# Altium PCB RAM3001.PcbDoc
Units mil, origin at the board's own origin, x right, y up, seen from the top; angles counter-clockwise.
Board outline 3500 x 2000 mil, 2 copper layers (Top Layer, Bottom Layer), stack 64.8 mil thick; 33 components, 89 nets, 343 pads, 69 vias.
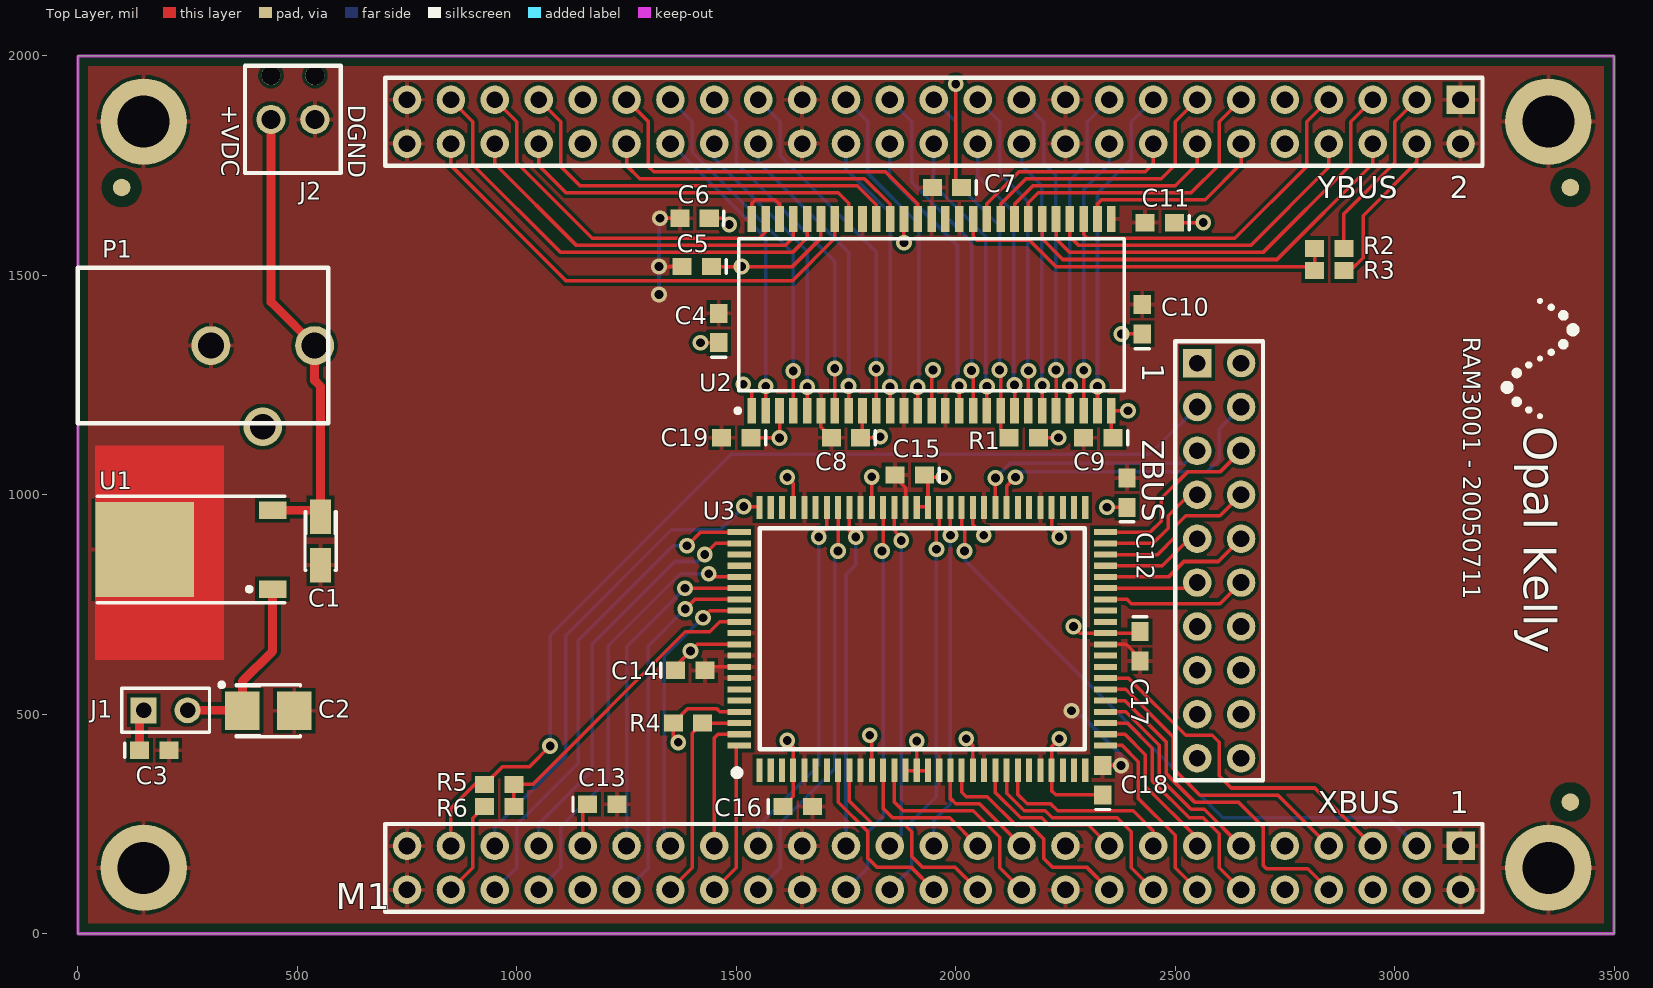
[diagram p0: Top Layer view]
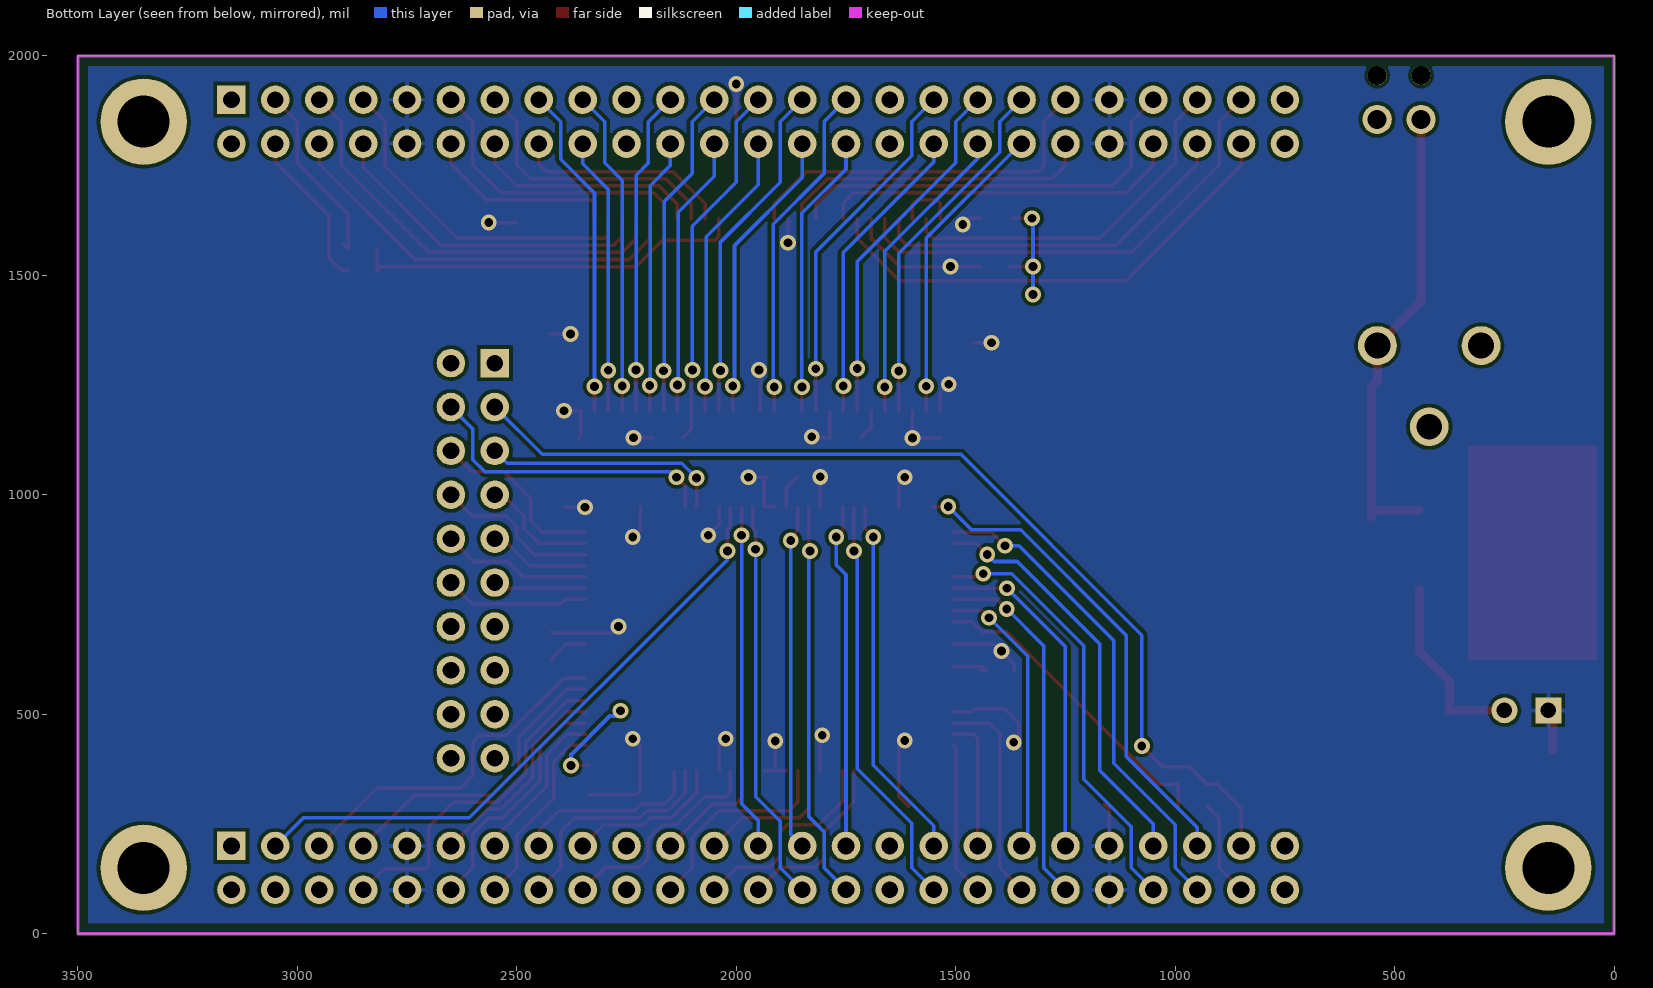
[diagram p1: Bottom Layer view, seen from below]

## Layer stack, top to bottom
Top Layer: signal copper 1.4
Dielectric: core 62, FR-4, Dk 4.8
Bottom Layer: signal copper 1.4

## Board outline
0,0 3500,0 3500,2000 0,2000

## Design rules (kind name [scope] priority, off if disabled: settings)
Clearance "Polygon Clearance" [InPolygon vs ((Not PadIsPlated) And (HoleSize = 0))] p1: gap=25
Clearance [All] p2: gap=8
ComponentClearance [All] p1: gap=10 collisioncheckmode=0 verticalgap=10
HoleSize [All] p1: absolutevalues=TRUE maxlimit=200 minlimit=1 maxpercent=80.000 minpercent=20.000
MinimumAnnularRing [All] p1: minimumring=8
PolygonConnect [All] p1: connectstyle=Relief reliefconductorwidth=10 reliefentries=4 polygonreliefangle="90 Angle"
RoutingVias [All] p1: holewidth=28 width=40 viastyle="Through Hole" minholewidth=20 minwidth=30 maxholewidth=40 maxwidth=70
SolderMaskExpansion [All] p1: expansion=4
TestPointUsage [All] p1: valid=0 allowmultiple=FALSE
Testpoint [All] p1: side=15 testpointundercomponent=TRUE minsize=40 maxsize=100 preferedsize=60 minholesize=0 maxholesize=40 preferedholesize=32 testpointgrid=1 style=1023 order=0123456789
Width [All] p1: maxlimit=24 minlimit=7 preferedwidth=7 toplayer_prefwidth=8 bottomlayer_prefwidth=10 minimp=50.000000 maximp=50.000000 favimp=50.000000
16 further rules are at their usual default settings.

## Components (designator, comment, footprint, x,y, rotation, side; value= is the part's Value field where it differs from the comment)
C1 "SM-A, 10v, 10%" TC3216-1206 553,895 r270 top
C2 "SM-A, 6.3v, 10%" TC3528-1411 434,508 r0 top
C3 "SM-0603, 10%, 16v" CC1608-0603 174,418 r0 top
C4 "SM-0603, 10%, 16v" CC1608-0603 1460,1380 r90 top
C5 "SM-0603, 10%, 16v" CC1608-0603 1410,1520 r180 top
C6 "SM-0603, 10%, 16v" CC1608-0603 1405,1630 r180 top
C7 "SM-0603, 10%, 16v" CC1608-0603 1980,1700 r180 top
C8 "SM-0603, 10%, 16v" CC1608-0603 1750,1130 r180 top
C9 "SM-0603, 10%, 16v" CC1608-0603 2325,1130 r180 top
C10 "SM-0603, 10%, 16v" CC1608-0603 2425,1400 r90 top
C11 "SM-0603, 10%, 16v" CC1608-0603 2465,1620 r180 top
C12 "SM-0603, 10%, 16v" CC1608-0603 2390,1005 r90 top
C13 "SM-0603, 10%, 16v" CC1608-0603 1195,295 r0 top
C14 "SM-0603, 10%, 16v" CC1608-0603 1395,600 r0 top
C15 "SM-0603, 10%, 16v" CC1608-0603 1895,1045 r180 top
C16 "SM-0603, 10%, 16v" CC1608-0603 1640,290 r0 top
C17 "SM-0603, 10%, 16v" CC1608-0603 2420,655 r270 top
C18 "SM-0603, 10%, 16v" CC1608-0603 2335,350 r90 top
C19 "SM-0603, 10%, 16v" CC1608-0603 1500,1130 r180 top
J1 "0.1\" spacing" HDR1X2 150,509 r0 top
J2 "2.54mm, 2-position" MPT-0.5/2-2.54 440,1855 r270 top
M1 "XEM3001" XEM3001MODULE 0,0 r0 top locked
P1 "2.1mm / 5.5mm" CUI-PJ102A 0,1340 r270 top locked
R1 "SM-0603, 5%, 1/10W" CR1608-0603 2155,1130 r180 top
R2 "SM-0603, 5%, 1/10W" CR1608-0603 2851,1561 r0 top
R3 "SM-0603, 5%, 1/10W" CR1608-0603 2851,1511 r0 top
R4 "SM-0603, 5%, 1/10W" CR1608-0603 1390,480 r0 top
R5 "SM-0603, 5%, 1/10W" CR1608-0603 960,340 r180 top
R6 "SM-0603, 5%, 1/10W" CR1608-0603 960,290 r180 top
U1 "1A, 3-pin DPAK" SIP-G3/Z11.05 298,875 r90 top
U2 "4Mbx16x4, TSOP" TSOP2-54 1945,1410 r0 top
U3 "2.5v/3.3v, 133 MHz, 256kx18" TQFP-100 1924,672 r0 top locked
? "OKLOGO" oklogotiny 3330.99,1441.5 r270 top

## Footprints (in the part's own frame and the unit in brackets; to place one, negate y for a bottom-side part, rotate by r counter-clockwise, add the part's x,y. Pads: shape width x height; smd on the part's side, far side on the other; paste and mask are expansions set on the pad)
CC1608-0603 [mm] "Chip Capacitor; Body 1.6 x 0.8 mm (LxW typ)"
  rect 1.1x1 smd: 1(-0.85,0) 2(0.85,0)
  silkscreen extent -1.7,-0.4 -1.7,0.4
CR1608-0603 [mm] "Chip Resistor; Body 1.6 x 0.8 mm (LxW typ)"
  rect 1.1x1 smd: 1(-0.85,0) 2(0.85,0)
CUI-PJ102A [mm] "2.1mm/5.5mm DC power jack"
  round 2.25 hole 1.5: 1(0,13.7) 2(0,7.7) 3(4.7,10.7)
  silkscreen extent -4.5,0 4.5,14.5
HDR1X2 [mm] "Connector; Header; 2 Position"
  rect 1.5x1.5 hole 0.9: 1(0,0)
  round 1.5 hole 0.9: 2(2.54,0)
  silkscreen extent -1.27,-1.27 3.81,1.27
MPT-0.5/2-2.54 [mm] "Terminal Block 1x2"
  round 1.1 hole 1.1: 0(-2.54,2.54) 0(-2.54,0)
  round 1.7 hole 1.1: 1(0,0) 2(0,2.54)
  silkscreen extent -3.1,-1.5 3.1,4.04
oklogotiny [mil] "Opal Kelly silkscreen logo (50 mil)."
  silkscreen extent -3,-82 266,83
SIP-G3/Z11.05 [mm] "D-PAK/TO-252-AA; 3 Leads (1 Cropped); Body 10.3 (inc. leads) x 6.7 mm (LxW max)"
  rect 1x1.6 smd: 1(-2.285,-3.7) 3(2.285,-3.7)
  rect 5.5x5.7 smd: 4(0,3.7)
  silkscreen extent -3.09,-4.4 3.09,6.45, body extent -3.3,-1.35 3.3,4.75, height 2.38
TC3216-1206 [mm] "Capacitor, SM Tantalum; Body 3.2 x 1.6 mm (LxW typ)"
  rect 2x1.2 smd: 1(-1.4,0) 2(1.4,0)
  silkscreen extent -1.7,-0.9 1.7,0.9
TC3528-1411 [mm] "Capacitor, SM Tantalum; Body 3.5 x 2.8 mm (LxW typ)"
  rect 2x2.2 smd: 1(-1.5,0) 2(1.5,0)
  silkscreen extent -2.82,-1.5 1.85,1.62
TQFP-100 [mm] "IPC Rectangular TQFP 100 Package"
  rect 0.35x1.35 smd: 1(-9.425,-7.6) 2(-8.775,-7.6) 3(-8.125,-7.6) 4(-7.475,-7.6) 5(-6.825,-7.6) 6(-6.175,-7.6) 7(-5.525,-7.6) 8(-4.875,-7.6) 9(-4.225,-7.6) 10(-3.575,-7.6) 11(-2.925,-7.6) 12(-2.275,-7.6) 13(-1.625,-7.6) 14(-0.975,-7.6) 15(-0.325,-7.6) 16(0.325,-7.6) 17(0.975,-7.6) 18(1.625,-7.6) 19(2.275,-7.6) 20(2.925,-7.6) 21(3.575,-7.6) 22(4.225,-7.6) 23(4.875,-7.6) 24(5.525,-7.6) 25(6.175,-7.6) 26(6.825,-7.6) 27(7.475,-7.6) 28(8.125,-7.6) 29(8.775,-7.6) 30(9.425,-7.6) 51(9.425,7.6) 52(8.775,7.6) 53(8.125,7.6) 54(7.475,7.6) 55(6.825,7.6) 56(6.175,7.6) 57(5.525,7.6) 58(4.875,7.6) 59(4.225,7.6) 60(3.575,7.6) 61(2.925,7.6) 62(2.275,7.6) 63(1.625,7.6) 64(0.975,7.6) 65(0.325,7.6) 66(-0.325,7.6) 67(-0.975,7.6) 68(-1.625,7.6) 69(-2.275,7.6) 70(-2.925,7.6) 71(-3.575,7.6) 72(-4.225,7.6) 73(-4.875,7.6) 74(-5.525,7.6) 75(-6.175,7.6) 76(-6.825,7.6) 77(-7.475,7.6) 78(-8.125,7.6) 79(-8.775,7.6) 80(-9.425,7.6)
  rect 1.35x0.35 smd: 31(10.6,-6.175) 32(10.6,-5.525) 33(10.6,-4.875) 34(10.6,-4.225) 35(10.6,-3.575) 36(10.6,-2.925) 37(10.6,-2.275) 38(10.6,-1.625) 39(10.6,-0.975) 40(10.6,-0.325) 41(10.6,0.325) 42(10.6,0.975) 43(10.6,1.625) 44(10.6,2.275) 45(10.6,2.925) 46(10.6,3.575) 47(10.6,4.225) 48(10.6,4.875) 49(10.6,5.525) 50(10.6,6.175) 81(-10.6,6.175) 82(-10.6,5.525) 83(-10.6,4.875) 84(-10.6,4.225) 85(-10.6,3.575) 86(-10.6,2.925) 87(-10.6,2.275) 88(-10.6,1.625) 89(-10.6,0.975) 90(-10.6,0.325) 91(-10.6,-0.325) 92(-10.6,-0.975) 93(-10.6,-1.625) 94(-10.6,-2.275) 95(-10.6,-2.925) 96(-10.6,-3.575) 97(-10.6,-4.225) 98(-10.6,-4.875) 99(-10.6,-5.525) 100(-10.6,-6.175)
  silkscreen extent -10.85,-7.87 9.4,6.4
TSOP2-54 [mm] "Plastic Small Outline; 54 Leads; Body Width 10.16 mm"
  rect 0.5x1.5 smd: 1(-10.4,-5.55) 2(-9.6,-5.55) 3(-8.8,-5.55) 4(-8,-5.55) 5(-7.2,-5.55) 6(-6.4,-5.55) 7(-5.6,-5.55) 8(-4.8,-5.55) 9(-4,-5.55) 10(-3.2,-5.55) 11(-2.4,-5.55) 12(-1.6,-5.55) 13(-0.8,-5.55) 14(0,-5.55) 15(0.8,-5.55) 16(1.6,-5.55) 17(2.4,-5.55) 18(3.2,-5.55) 19(4,-5.55) 20(4.8,-5.55) 21(5.6,-5.55) 22(6.4,-5.55) 23(7.2,-5.55) 24(8,-5.55) 25(8.8,-5.55) 26(9.6,-5.55) 27(10.4,-5.55) 28(10.4,5.55) 29(9.6,5.55) 30(8.8,5.55) 31(8,5.55) 32(7.2,5.55) 33(6.4,5.55) 34(5.6,5.55) 35(4.8,5.55) 36(4,5.55) 37(3.2,5.55) 38(2.4,5.55) 39(1.6,5.55) 40(0.8,5.55) 41(0,5.55) 42(-0.8,5.55) 43(-1.6,5.55) 44(-2.4,5.55) 45(-3.2,5.55) 46(-4,5.55) 47(-4.8,5.55) 48(-5.6,5.55) 49(-6.4,5.55) 50(-7.2,5.55) 51(-8,5.55) 52(-8.8,5.55) 53(-9.6,5.55) 54(-10.4,5.55)
  silkscreen extent -11.33,-5.67 11.15,4.4
XEM3001MODULE [mil]
  round 196.85 hole 118.11: 0(150,150) 0(150,1850) 0(3350,150) 0(3350,1850)
  rect 65x65 hole 38: X1(3150,200) Y1(3150,1900) Z1(2550,1300)
  round 65 hole 38: X2(3150,100) X3(3050,200) X4(3050,100) X5(2950,200) X6(2950,100) X7(2850,200) X8(2850,100) X9(2750,200) X10(2750,100) X11(2650,200) X12(2650,100) X13(2550,200) X14(2550,100) X15(2450,200) X16(2450,100) X17(2350,200) X18(2350,100) X19(2250,200) X20(2250,100) X21(2150,200) X22(2150,100) X23(2050,200) X24(2050,100) X25(1950,200) X26(1950,100) X27(1850,200) X28(1850,100) X29(1750,200) X30(1750,100) X31(1650,200) X32(1650,100) X33(1550,200) X34(1550,100) X35(1450,200) X36(1450,100) X37(1350,200) X38(1350,100) X39(1250,200) X40(1250,100) X41(1150,200) X42(1150,100) X43(1050,200) X44(1050,100) X45(950,200) X46(950,100) X47(850,200) X48(850,100) X49(750,200) X50(750,100) Y2(3150,1800) Y3(3050,1900) Y4(3050,1800) Y5(2950,1900) Y6(2950,1800) Y7(2850,1900) Y8(2850,1800) Y9(2750,1900) Y10(2750,1800) Y11(2650,1900) Y12(2650,1800) Y13(2550,1900) Y14(2550,1800) Y15(2450,1900) Y16(2450,1800) Y17(2350,1900) Y18(2350,1800) Y19(2250,1900) Y20(2250,1800) Y21(2150,1900) Y22(2150,1800) Y23(2050,1900) Y24(2050,1800) Y25(1950,1900) Y26(1950,1800) Y27(1850,1900) Y28(1850,1800) Y29(1750,1900) Y30(1750,1800) Y31(1650,1900) Y32(1650,1800) Y33(1550,1900) Y34(1550,1800) Y35(1450,1900) Y36(1450,1800) Y37(1350,1900) Y38(1350,1800) Y39(1250,1900) Y40(1250,1800) Y41(1150,1900) Y42(1150,1800) Y43(1050,1900) Y44(1050,1800) Y45(950,1900) Y46(950,1800) Y47(850,1900) Y48(850,1800) Y49(750,1900) Y50(750,1800) Z2(2650,1300) Z3(2550,1200) Z4(2650,1200) Z5(2550,1100) Z6(2650,1100) Z7(2550,1000) Z8(2650,1000) Z9(2550,900) Z10(2650,900) Z11(2550,800) Z12(2650,800) Z13(2550,700) Z14(2650,700) Z15(2550,600) Z16(2650,600) Z17(2550,500) Z18(2650,500) Z19(2550,400) Z20(2650,400)
  silkscreen extent 700,50 3200,1950

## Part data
C1 C2: library part "Capacitor Pol", "Tantalum capacitor"
C3 C4 C5 C6 C7 C8 C9 C10 C11 C12 C13 C14 C15 C16 C17 C18 C19: library part Capacitor, "Ceramic capacitor"
J1: library part "Jumper 1X2", "Header"
J2: library part "Terminal 1x2", "Terminal block connector"
M1: "XEM3001 Module Connector"
P1: library part DCPOWER, "DC power connector"
R1 R2 R3 R4 R5 R6: library part Resistor, "Thick-film resistor"
U1: library part LP8340CDT, "LDO Regulator"
U2: library part MT48LC16M16A2TG-7E, "32MB SDRAM"
U3: library part CY7C1352G, "4Mb Pipelined SRAM, NoBL"
?: "Opal Kelly PCB Logo"

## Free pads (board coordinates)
  round 40 smd mask+20: FD0(100,1700) FD1(3400,1700) FD2(3400,300)

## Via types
v1: diameter 36, hole 20, Top Layer to Bottom Layer, tented both sides, 69 vias

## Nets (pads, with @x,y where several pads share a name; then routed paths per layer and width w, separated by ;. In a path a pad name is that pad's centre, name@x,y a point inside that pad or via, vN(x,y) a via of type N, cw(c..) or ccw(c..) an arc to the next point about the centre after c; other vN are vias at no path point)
+3.3VDD: C3.1 C4.1 C5.1 C6.1 C7.1 C8.1 C9.1 C10.1 C11.1 C12.1 C13.1 C14.1 C15.1 C16.1 C17.1 C18.1 C19.1 J1.1 M1.X9 M1.X10 M1.X41 M1.X42 M1.Y9 M1.Y10 M1.Y41 M1.Y42 R1.1 R4.1 U2.1 U2.3 U2.9 U2.14 U2.27 U2.43 U2.49 U3.4 U3.11 U3.14 U3.15 U3.16 U3.20 U3.27 U3.41 U3.54 U3.61 U3.65 U3.66 U3.70 U3.77 U3.91 U3.97 | length 3266.3
  Top Layer w8: M1.X41 1150,283.46 C13.1 ; v1@1356.54,435.46 R4.1 1388.54,512 1456,512 1462.34,505.66 U3.97@1504.71,505.66 ; C14.1@1366.54,600 1366.54,614.54 1411.2,659.2 U3.91@1504.71,659.2 ; v1(1418.54,1346.54) C4.1 ; C5.1 1628,1520 1693.03,1585.03 U2.49 ; C6.1@1443.46,1630 1470,1630 v1(1484,1616) ; v1(1516,1252) 1535.55,1232.45 U2.1 ; C19.1 1598,1130 v1(1598.54,1129.46) U2.3 ; C16.1 1629.71,313.17 1629.71,426.29 v1(1616,440) ; v1(1616,1040) 1629.71,1026.29 U3.77@1629.71,973.18 ; U2.9 1787.52,1134.06 C8.1 1826,1130 v1(1828,1132) ; v1(1804,452) 1808.84,447.16 U3.11@1808.84,370.82 ; U3.70@1808.84,973.18 v1(1808.84,1040.84) ; v1(1882.01,1574.01) U2.43 ; U3.14@1885.61,370.82 U3.16@1936.8,370.82 ; U3.15@1911.2,370.82 v1(1911.2,439.2) ; U3.66@1911.2,973.18 1936.8,973.18 1936.8,1038.33 C15.1@1938.46,1040 ; C15.1@1928.46,1040 v1(1972,1040) ; U2.14 1945,1281 v1(1948,1284) ; v1(2000,1936) 2000,1713.46 C7.1 ; v1(2024,444) 2039.16,428.84 U3.20@2039.16,370.82 ; U3.61@2039.16,973.18 2039.16,932.84 v1(2064,908) ; R1.1 v1(2234,1130) ; U3.54@2218.29,973.18 2218.29,921.71 v1(2236,904) ; v1(2236,444) 2218.29,426.29 2218.29,325.71 2227.46,316.54 C18.1 ; v1(2268,700) 2283.2,684.8 2416.33,684.8 C17.1 ; v1(2344.47,971.53) C12.1 ; C9.1 2354.45,1134.02 U2.27 v1(2392.5,1191.5) ; v1(2377.46,1366.54) C10.1 ; C11.1 v1(2564,1620)
  Top Layer w20: C3.1@139,419.54 C3.1 140.54,499.54 J1.1
  other v1: 1368,436 1396,644 1512,1520
+VDC: C1.1 J2.1 P1.1 U1.3 | length 1084.8
  Top Layer w20: J2.1 440,1439.37 P1.1@553,1326.37 ; U1.3 542.1,964.96 C1.1@553,954.06 ; P1.1 539.37,1260.63 553,1247 C1.1
DGND: C1.2 C2.2 C3.2 C4.2 C5.2 C6.2 C7.2 C8.2 C9.2 C10.2 C11.2 C12.2 C13.2 C14.2 C15.2 C16.2 C17.2 C18.2 C19.2 J2.2 M1.0 M1.X1 M1.X2 M1.X19 M1.X20 M1.X31 M1.X32 M1.X49 M1.X50 M1.Y1 M1.Y2 M1.Y19 M1.Y20 M1.Y31 M1.Y32 M1.Y49 M1.Y50 P1.2 U1.4 U2.6 U2.12 U2.15 U2.28 U2.39 U2.41 U2.46 U2.52 U2.54 U3.5 U3.10 U3.17 U3.21 U3.26 U3.40 U3.55 U3.60 U3.67 U3.71 U3.76 U3.90 U3.92 U3.93 U3.94 | length 954.4
  Top Layer w8: v1(1324,1520) C5.2 ; v1(1326,1630) C6.2 ; C14.2 C14.2@1444,600 ; C14.2@1436.49,608.02 U3.93@1504.71,608.02 ; U2.54 1535.55,1663.55 1544,1672 1588,1672 1598.54,1661.46 U2.52 ; U2.6 1693.03,1153.5 C8.2 ; C15.2@1861.54,1040 1885.61,1015.92 U3.67@1885.61,973.18 ; C18.2 v1(2376.54,383.46) ; U3.40@2343.29,659.2 2388.8,659.2 2420,628 C17.2
  Bottom Layer w8: v1(1324,1456) 1324,1628 v1(1326,1630)
  Bottom Layer w10: v1@2264,496 2288,496 2376.54,407.46 v1(2376.54,383.46)
  other v1: 2264,508
NetC2_1: C2.1 J1.2 U1.1 | length 430.9
  Top Layer w20: J1.2 373.94,509 C2.1 374.94,574.94 443.67,643.67 U1.1
NetM1_X47: M1.X47 M1.Z3 R5.2 | length 2312.2
  Top Layer w8: M1.X47 850,286 904,340 R5.2 966.54,380 1028,380 v1(1076,428)
  Bottom Layer w8: v1(1076,428) 1076,680 1488,1092 2442,1092 M1.Z3
NetM1_X48: M1.X48 R6.2 | length 221.7
  Top Layer w8: M1.X48 900,150 900,263.46 R6.2
NetM1_Y3: M1.Y3 R2.2 | length 423.9
  Top Layer w8: R2.2@2896,1572.54 R2.2 2884.46,1640.46 3000,1756 3000,1850 M1.Y3
NetM1_Y4: M1.Y4 R3.2 | length 366.1
  Top Layer w8: R3.2 2899,1511 2928,1540 2928,1636 3050,1758 M1.Y4
SDRAM_A0: M1.Y21 U2.23 | length 743
  Top Layer w8: U2.23 v1(2228.46,1284.46)
  Bottom Layer w8: M1.Y21@2152,1900 M1.Y21 2200,1850 2200,1756 2228,1728 2228,1284.93 v1(2228.46,1284.46)
SDRAM_A1: M1.Y17 U2.24 | length 745.8
  Top Layer w8: U2.24 v1(2259.96,1248.04)
  Bottom Layer w8: v1(2259.96,1248.04) 2259.96,1715.96 2300,1756 2300,1850 M1.Y17
SDRAM_A2: M1.Y18 U2.25 | length 632.8
  Top Layer w8: U2.25 v1(2291.46,1283.46)
  Bottom Layer w8: v1(2291.46,1283.46) 2291.46,1695.46 2350,1754 M1.Y18
SDRAM_A3: M1.Y15 U2.26 | length 761.1
  Top Layer w8: U2.26 v1(2322.95,1246.95)
  Bottom Layer w8: v1(2322.95,1246.95) 2322.95,1686.95 2400,1764 2400,1850 M1.Y15
SDRAM_A4: M1.Y12 U2.29 | length 445.2
  Top Layer w8: U2.29 2322.95,1662.95 2332,1672 2568,1672 2650,1754 M1.Y12
SDRAM_A5: M1.Y7 U2.30 | length 788.7
  Top Layer w8: U2.30 2291.46,1592.54 2300,1584 2636,1584 2800,1748 2800,1850 M1.Y7
SDRAM_A6: M1.Y8 U2.31 | length 766.5
  Top Layer w8: U2.31 2259.96,1588.04 2280,1568 2672,1568 2850,1746 M1.Y8
SDRAM_A7: M1.Y5 U2.32 | length 981.1
  Top Layer w8: U2.32 2228.46,1583.54 2260,1552 2700,1552 2900,1752 2900,1850 M1.Y5
SDRAM_A8: M1.Y6 U2.33 | length 954.3
  Top Layer w8: U2.33 2196.97,1583.03 2244,1536 2732,1536 2950,1754 M1.Y6
SDRAM_A9: M1.Y11 U2.34 | length 676
  Top Layer w8: U2.34 2165.47,1665.47 2188,1688 2536,1688 2600,1752 2600,1850 M1.Y11
SDRAM_A10: M1.Y22 U2.22 | length 628
  Top Layer w8: U2.22 v1(2196.97,1248.97)
  Bottom Layer w8: M1.Y22 2150,1750 2196,1704 2196,1249.94 v1(2196.97,1248.97)
SDRAM_A11: M1.Y14 U2.35 | length 533.6
  Top Layer w8: U2.35 2133.98,1661.98 2176,1704 2500,1704 2550,1754 M1.Y14
SDRAM_A12: M1.Y13 U2.36 | length 637.3
  Top Layer w8: U2.36 2102.48,1662.48 2160,1720 2468,1720 2500,1752 2500,1850 M1.Y13
SDRAM_BA0: M1.Y24 U2.20 | length 643.3
  Top Layer w8: U2.20 v1(2133.98,1250.02)
  Bottom Layer w8: M1.Y24 2050,1726 2132,1644 2132,1252 v1(2133.98,1250.02)
SDRAM_BA1: M1.Y23 U2.21 | length 756.3
  Top Layer w8: U2.21 v1(2165.47,1282.53)
  Bottom Layer w8: M1.Y23 2100,1850 2100,1732 2164,1668 2164,1284 v1(2165.47,1282.53)
SDRAM_CAS: M1.Y27 U2.17 | length 787
  Top Layer w8: v1(2036,1282.98) 2039.49,1279.49 U2.17
  Bottom Layer w8: M1.Y27 1900,1850 1900,1712 2036,1576 v1(2036,1282.98)
SDRAM_CKE: M1.Y16 U2.37 | length 497.2
  Top Layer w8: U2.37 2070.98,1662.98 2144,1736 2432,1736 2450,1754 M1.Y16
SDRAM_CLK: R2.1 R3.1 U2.38 | length 900.1
  Top Layer w8: U2.38 2039.49,1588.51 2048,1580 2168,1580 2228,1520 2808.54,1520 R3.1 R2.1
SDRAM_CS: M1.Y25 R1.2 U2.19 | length 841.1
  Top Layer w8: v1(2100,1284) 2102.48,1281.52 2102.48,1149.06 R1.2
  Bottom Layer w8: M1.Y25 2000,1850 2000,1712 2100,1612 v1(2100,1284)
SDRAM_D0: M1.Y38 U2.2 | length 699.6
  Top Layer w8: U2.2 v1(1567.05,1247.05)
  Bottom Layer w8: M1.Y38 1352,1800 1567.05,1584.95 v1(1567.05,1247.05)
SDRAM_D1: M1.Y37 U2.4 | length 824.5
  Top Layer w8: U2.4 v1(1630.04,1282.04)
  Bottom Layer w8: M1.Y37 1400,1850 1400,1780 1630.04,1549.96 v1(1630.04,1282.04)
SDRAM_D2: M1.Y36 U2.5 | length 696.1
  Top Layer w8: U2.5 v1(1661.54,1245.54)
  Bottom Layer w8: M1.Y36 1450,1766 1661.54,1554.46 v1(1661.54,1245.54)
SDRAM_D3: M1.Y35 U2.7 | length 822.2
  Top Layer w8: U2.7 v1(1724.53,1287.47)
  Bottom Layer w8: M1.Y35 1500,1850 1500,1756 1724.53,1531.47 v1(1724.53,1287.47)
SDRAM_D4: M1.Y34 U2.8 | length 693.8
  Top Layer w8: U2.8 v1(1756.02,1247.98)
  Bottom Layer w8: M1.Y34 1550,1758 1756.02,1551.98 v1(1756.02,1247.98)
SDRAM_D5: M1.Y33 U2.10 | length 819.9
  Top Layer w8: U2.10 v1(1819.02,1287.02)
  Bottom Layer w8: M1.Y33 1600,1850 1600,1772 1819.02,1552.98 v1(1819.02,1287.02)
SDRAM_D6: M1.Y30 U2.11 | length 650.1
  Top Layer w8: U2.11 v1(1850.51,1245.49)
  Bottom Layer w8: M1.Y30 1750,1742 1850.51,1641.49 v1(1850.51,1245.49)
SDRAM_D7: M1.Y29 U2.13 | length 778.3
  Top Layer w8: U2.13 v1(1913.5,1245.5)
  Bottom Layer w8: M1.Y29 1800,1850 1800,1732 1916,1616 1916,1248 v1(1913.5,1245.5)
SDRAM_D8: M1.Y39 U2.42 | length 855.6
  Top Layer w8: M1.Y39 1300,1850 1300,1748 1312,1736 1840,1736 1913.5,1662.5 U2.42
SDRAM_D9: M1.Y40 U2.44 | length 720.2
  Top Layer w8: M1.Y40 1250,1750 1280,1720 1792,1720 1850.51,1661.49 U2.44
SDRAM_D10: M1.Y43 U2.45 | length 960.2
  Top Layer w8: M1.Y43 1100,1850 1100,1748 1144,1704 1776,1704 1819.02,1660.98 U2.45
SDRAM_D11: M1.Y44 U2.47 | length 827.1
  Top Layer w8: M1.Y44 1050,1750 1112,1688 1732,1688 1756.02,1663.98 U2.47
SDRAM_D12: M1.Y48 U2.48 | length 1117
  Top Layer w8: M1.Y48 850,1750 1112,1488 1628,1488 1724.53,1584.53 U2.48
SDRAM_D13: M1.Y47 U2.50 | length 1069.9
  Top Layer w8: M1.Y47 900,1850 900,1752 1100,1552 1628,1552 1661.54,1585.54 U2.50
SDRAM_D14: M1.Y46 U2.51 | length 853
  Top Layer w8: M1.Y46 950,1754 1136,1568 1612,1568 1630.04,1586.04 U2.51
SDRAM_D15: M1.Y45 U2.53 | length 838.7
  Top Layer w8: M1.Y45 1000,1850 1000,1756 1172,1584 1552,1584 1567.05,1599.05 U2.53
SDRAM_RAS: M1.Y26 U2.18 | length 658.6
  Top Layer w8: U2.18 v1(2070.98,1246.98)
  Bottom Layer w8: M1.Y26 1950,1706 2068,1588 2068,1249.97 v1(2070.98,1246.98)
SDRAM_WE: M1.Y28 U2.16 | length 673.9
  Top Layer w8: U2.16 v1(2007.99,1247.99)
  Bottom Layer w8: M1.Y28 1850,1722 2004,1568 2004,1251.98 v1(2007.99,1247.99)
SRAM_A0: M1.X5 U3.37 | length 809.6
  Top Layer w8: U3.37@2343.29,582.43 2393.57,582.43 2524,452 2584,452 2600,436 2600,360 2628,332 2818,332 M1.X5
SRAM_A1: M1.X7 U3.36 | length 696.7
  Top Layer w8: U3.36@2343.29,556.84 2387.16,556.84 2496,448 2496,376 2556,316 2734,316 M1.X7
SRAM_A2: M1.X8 U3.35 | length 779.1
  Top Layer w8: U3.35@2343.29,531.25 2384.75,531.25 2480,436 2480,364 2544,300 2644,300 2700,244 2700,156 2708,148 2802,148 M1.X8
SRAM_A3: M1.X11 U3.34 | length 476.3
  Top Layer w8: U3.34@2343.29,505.66 2387.71,505.66 2464,429.37 2464,356 2536,284 2566,284 M1.X11
SRAM_A4: M1.X12 U3.33 | length 553.2
  Top Layer w8: U3.33@2343.29,480.07 2390.67,480.07 2448,422.75 2448,348 2532,264 2563.37,264 2600,227.37 2600,150 M1.X12
SRAM_A5: M1.X13 U3.32 | length 366.8
  Top Layer w8: U3.32@2343.29,454.48 2385.52,454.48 2432,408 2432,336 2550,218 M1.X13 M1.X13@2548,200
SRAM_A6: M1.X36 U3.100 | length 351.6
  Top Layer w8: M1.X36 1500,150 1500,424.18 U3.100@1504.71,428.89
SRAM_A7: M1.X35 U3.99 | length 304.2
  Top Layer w8: M1.X35 1450,446 1458.48,454.48 U3.99@1504.71,454.48
SRAM_A8: M1.X43 U3.82 | length 938.3
  Top Layer w8: v1(1428,864) 1453.52,889.52 U3.82@1504.71,889.52
  Bottom Layer w8: M1.X43 1050,250 1172,372 1172,660 1360,848 1412,848 v1(1428,864)
SRAM_A9: M1.X46 U3.81 | length 1113.8
  Top Layer w8: v1(1388,884) 1419.11,915.11 U3.81@1504.71,915.11
  Bottom Layer w8: M1.X46 1000,150 1000,248 1140,388 1140,668 1356,884 v1(1388,884)
SRAM_A10: M1.X45 U3.80 | length 1109.5
  Top Layer w8: v1(1517.18,973.18) U3.80@1552.94,973.18
  Bottom Layer w8: M1.X45 950,242 1112,404 1112,680 1352,920 1464,920 v1(1517.18,973.18)
SRAM_A11: M1.Z12 U3.44 | length 330.6
  Top Layer w8: U3.44@2343.29,761.57 2390.43,761.57 2400,752 2602,752 M1.Z12
SRAM_A12: M1.Z11 U3.45 | length 212
  Top Layer w8: U3.45@2343.29,787.16 2537.16,787.16 M1.Z11
SRAM_A13: M1.Z10 U3.46 | length 342.8
  Top Layer w8: U3.46@2343.29,812.75 2484.75,812.75 2520,848 2598,848 M1.Z10
SRAM_A14: M1.Z9 U3.47 | length 232.2
  Top Layer w8: U3.47@2343.29,838.34 2470.34,838.34 2532,900 M1.Z9
SRAM_A15: M1.Z8 U3.48 | length 377.1
  Top Layer w8: U3.48@2343.29,863.93 2459.93,863.93 2500,904 2500,928 2524,952 2602,952 M1.Z8
SRAM_A16: M1.Z7 U3.49 | length 268.9
  Top Layer w8: U3.49@2343.29,889.52 2449.52,889.52 2484,924 2484,952 2532,1000 M1.Z7
SRAM_A17: M1.Z6 U3.50 | length 413.8
  Top Layer w8: U3.50@2343.29,915.11 2443.11,915.11 2468,940 2468,992 2528,1052 2602,1052 M1.Z6
SRAM_ADV_LD: M1.X44 U3.85 | length 989.1
  Top Layer w8: v1(1437.5,820) 1444.75,812.75 U3.85@1504.71,812.75
  Bottom Layer w8: M1.X44 1100,150 1100,244 1208,352 1208,656 1372,820 v1(1437.5,820)
SRAM_CE1: M1.X38 R4.2 U3.98 | length 491.7
  Top Layer w8: M1.X38 1400,150 1400,456.54 1423.54,480.07 U3.98@1504.71,480.07
SRAM_CEN: M1.X40 U3.87 | length 825.1
  Top Layer w8: v1(1384,740) 1405.57,761.57 U3.87@1504.71,761.57
  Bottom Layer w8: M1.X40 1300,150 1300,656 v1(1384,740)
SRAM_CLK: R5.1 R6.1 U3.89 | length 714.7
  Top Layer w8: R6.1 R5.1 1036,340 1384,688 1440,688 1462.39,710.39 U3.89@1504.71,710.39
SRAM_D0: M1.Z4 U3.58 | length 696.4
  Top Layer w8: U3.58@2115.93,973.18 2115.93,1019.93 v1(2136,1040)
  Bottom Layer w8: v1(2136,1040) 2148,1052 2572,1052 2600,1080 2600,1150 M1.Z4
SRAM_D1: M1.Z5 U3.59 | length 550.4
  Top Layer w8: U3.59@2090.34,973.18 v1(2090.34,1038.34)
  Bottom Layer w8: v1(2090.34,1038.34) 2124,1072 2522,1072 M1.Z5
SRAM_D2: M1.X3 U3.62 | length 1423.9
  Top Layer w8: U3.62@2013.57,973.18 2013.57,926.43 2020,920 v1(2020,872)
  Bottom Layer w8: v1(2020,872) 2020,852 2608,264 2986,264 M1.X3
SRAM_D3: M1.X25 U3.63 | length 788.9
  Top Layer w8: v1(1987.98,908.02) U3.63@1987.98,973.18
  Bottom Layer w8: M1.X25 1950,258 1987.98,295.98 v1(1987.98,908.02)
SRAM_D4: M1.X27 U3.68 | length 791.6
  Top Layer w8: U3.68@1860.02,973.18 1860.02,919.98 v1(1876,896)
  Bottom Layer w8: M1.X27@1848,202 M1.X27 1876,226 v1(1876,896)
SRAM_D5: M1.X30 U3.69 | length 908.2
  Top Layer w8: v1@1834.43,881.57 U3.69@1834.43,973.18
  Bottom Layer w8: M1.X30 1800,150 1800,232 1834.43,266.43 v1@1834.43,881.57
  other v1: 1832,872
SRAM_D6: M1.X29 U3.72 | length 791.1
  Top Layer w8: U3.72@1757.66,973.18 1757.66,918.34 v1(1772,904)
  Bottom Layer w8: M1.X29@1748,202 M1.X29 1750,818 1772,840 v1(1772,904)
SRAM_D7: M1.X34 U3.73 | length 948.6
  Top Layer w8: v1(1732.07,872.07) U3.73@1732.07,973.18
  Bottom Layer w8: M1.X34 1600,150 1600,252 1724,376 1724,864 v1(1732.07,872.07)
SRAM_D8: M1.X26 U3.8 | length 406.8
  Top Layer w8: U3.8@1732.07,370.82 1732.07,299.93 1800,232 1800,172 1820,152 1898,152 M1.X26
SRAM_D9: M1.X24 U3.9 | length 477.4
  Top Layer w8: U3.9@1757.66,370.82 1757.66,302.34 1812,248 1884,248 1900,232 1900,176 1924,152 1998,152 M1.X24
SRAM_D10: M1.X23 U3.12 | length 336.3
  Top Layer w8: U3.12@1834.43,370.82 1834.43,285.57 1856,264 1986,264 M1.X23
SRAM_D11: M1.X22 U3.13 | length 484.7
  Top Layer w8: U3.13@1860.02,370.82 1860.02,299.98 1880,280 2040,280 2100,220 2100,150 M1.X22
SRAM_D12: M1.X21 U3.18 | length 269.6
  Top Layer w8: U3.18@1987.98,370.82 1987.98,308.02 2000,296 2054,296 M1.X21
SRAM_D13: M1.X18 U3.19 | length 502.7
  Top Layer w8: U3.19@2013.57,370.82 2013.57,322.43 2024,312 2072,312 2136,248 2168,248 2200,216 2200,172 2220,152 2298,152 M1.X18
SRAM_D14: M1.X17 U3.22 | length 359.2
  Top Layer w8: U3.22@2090.34,370.82 2090.34,321.66 2148,264 2196,264 2212,248 2302,248 M1.X17
SRAM_D15: M1.X16 U3.23 | length 524
  Top Layer w8: U3.23@2115.93,370.82 2115.93,320.07 2156,280 2204,280 2220,264 2368,264 2400,232 2400,150 M1.X16
SRAM_MODE: M1.X14 U3.31 | length 435.5
  Top Layer w8: U3.31@2343.29,428.89 2379.11,428.89 2416,392 2416,308 2500,224 2500,150 M1.X14
SRAM_OE: M1.X39 U3.86 | length 763.9
  Top Layer w8: v1(1383.16,787.16) U3.86@1504.71,787.16
  Bottom Layer w8: M1.X39 1250,654 v1(1383.16,787.16)
SRAM_P1: M1.X33 U3.74 | length 838
  Top Layer w8: v1(1688,904) 1706.48,922.48 U3.74@1706.48,973.18
  Bottom Layer w8: M1.X33 1550,246 1688,384 v1(1688,904)
SRAM_P2: M1.X15 U3.24 | length 430.6
  Top Layer w8: U3.24@2141.52,370.82 2141.52,317.11 2162.63,296 2216,296 2232,280 2404,280 2450,234 M1.X15
SRAM_WE: M1.X37 U3.88 | length 649.6
  Top Layer w8: v1(1424,720) 1439.98,735.98 U3.88@1504.71,735.98
  Bottom Layer w8: M1.X37 1336,214 1336,632 v1(1424,720)
SRAM_ZZ: M1.X28 U3.64 | length 919.7
  Top Layer w8: v1(1956,876) 1956,917.29 1962.39,923.68 U3.64@1962.39,973.18
  Bottom Layer w8: M1.X28 1900,150 1900,256 1956,312 v1(1956,876)
pads on no net: J2.0 M1.X4 M1.X6 M1.Z1 M1.Z2 M1.Z13 M1.Z14 M1.Z15 M1.Z16 M1.Z17 M1.Z18 M1.Z19 M1.Z20 P1.3 U2.40 U3.1 U3.2 U3.3 U3.6 U3.7 U3.25 U3.28 U3.29 U3.30 U3.38 U3.39 U3.42 U3.43 U3.51 U3.52 U3.53 U3.56 U3.57 U3.75 U3.78 U3.79 U3.83 U3.84 U3.95 U3.96

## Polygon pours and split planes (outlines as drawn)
DGND on Top Layer (solid, remove dead copper): 24,24 3476,24 3476,1976 24,1976
+3.3VDD on Bottom Layer (solid, remove dead copper): 24,24 3476,24 3476,1976 24,1976

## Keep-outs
Keep-Out Layer:
  the board outline again, w7

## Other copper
Top Layer:
  region net DGND: 40,1112 332,1112 332,624 40,624

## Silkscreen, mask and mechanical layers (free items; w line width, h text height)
Top Overlay:
  text "+VDC" at 328,1888 h40 r270
  text "DGND" at 616,1888 h40 r270
  text "RAM3001 - 20050711" at 3156,1360 h40 r270

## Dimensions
0,2000 to 0,0 on Mechanical 1
0,0 to 3500,0 on Mechanical 1
150,1850 to 3350,1850 on Mechanical 1
3350,1850 to 3150,1900 on Mechanical 1
3150,1900 to 3350,1850 on Mechanical 1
